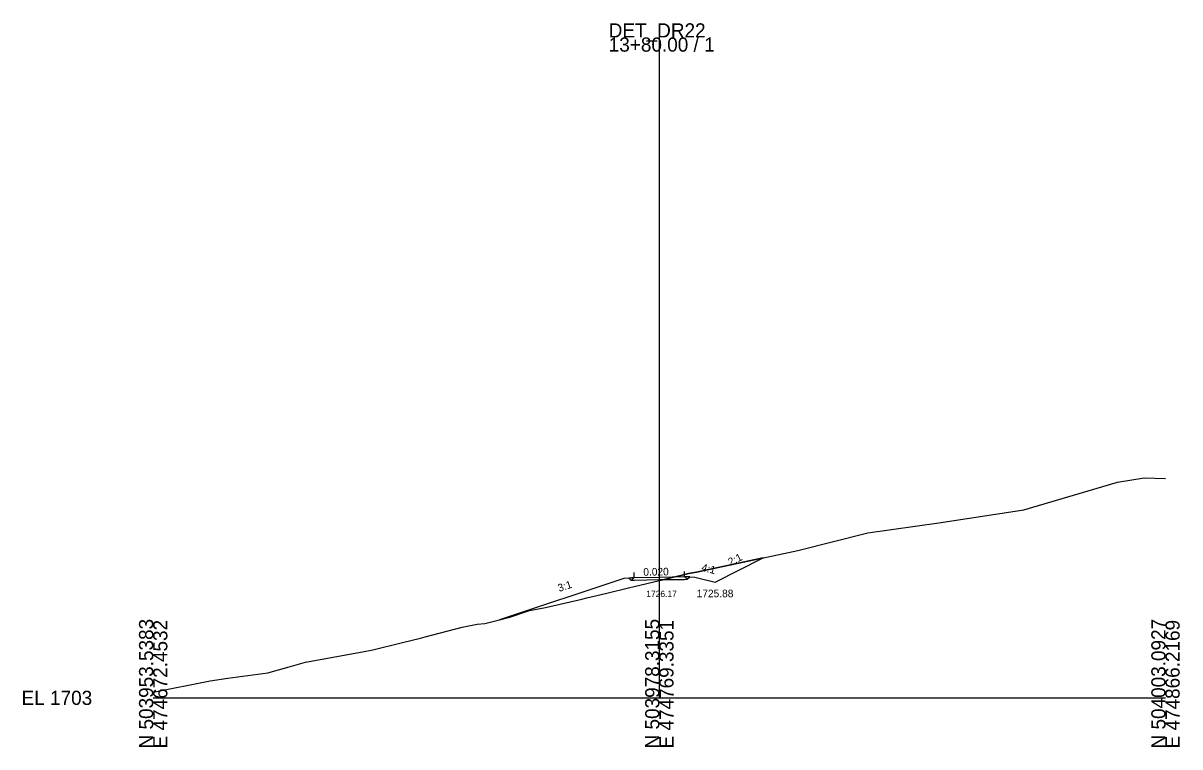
# Model space of a CAD drawing. Extents: x -26 to 1203, y -10 to 9633.
# Drawn here: x -25.7 to 202.8, y 9490.3 to 9633.4 of the extents above; entities that cross this region are included whole.
import ezdxf

# ---------------------------------------------------------------- set-up
doc = ezdxf.new("R2010")
doc.units = 0
for name, color, linetype in [('Exist Cross Section Cell', 7, 'Continuous'), ('Exist XS Center Line Elevation Label', 7, 'Continuous'), ('Exist XS Ground Line', 7, 'Continuous'), ('Prop XS Ditch Slope Text', 7, 'Continuous'), ('Prop XS Ditch Standard Text', 7, 'Continuous'), ('Prop XS Earthwork Shape', 7, 'Continuous'), ('Prop XS EOT Tick Mark', 7, 'Continuous'), ('Prop XS Finish Grade', 7, 'Continuous'), ('Prop XS Finish Grade Earthwork', 7, 'Continuous'), ('Prop XS Finish Grade Pavement', 7, 'Continuous'), ('Prop XS Pvmt Edge Slope', 7, 'Continuous'), ('Prop XS SE Text', 7, 'Continuous'), ('Prop XS Shoulder Borrow Shape', 7, 'Continuous'), ('Prop XS Side Slope Text', 7, 'Continuous'), ('Prop XS Subgrade Earthwork', 7, 'Continuous')]:
    doc.layers.add(name, color=color, linetype=linetype)

msp = doc.modelspace()

# ---------------------------------------------------------------- linework, layer by layer
at = {"layer": 'Exist Cross Section Cell'}
for p, q in [((100, 9500), (100, 9630.52)), ((0, 9500), (100, 9500)), ((100, 9500), (200, 9500))]:
    msp.add_line(p, q, dxfattribs=at)
at = {"layer": 'Exist XS Ground Line'}
msp.add_lwpolyline([(0, 9501.1), (11.27, 9503.38), (14.77, 9503.87), (22.65, 9504.95), (26.88, 9506.1), (30.1, 9507.02), (41.38, 9509.12), (43.4, 9509.52), (49.26, 9510.91), (52.81, 9511.81), (53.72, 9512.03), (61.03, 9513.96), (64.04, 9514.57), (65.53, 9514.67), (70.45, 9515.92), (74.37, 9517.25), (77.48, 9517.87), (84.69, 9519.49), (85.7, 9519.74), (89.63, 9520.66), (93.92, 9521.73), (95.02, 9522), (100, 9523.17), (105.07, 9524.35), (105.74, 9524.6), (107.31, 9524.83), (109.81, 9525.37), (127.36, 9529.1), (141.18, 9532.64), (155.23, 9534.62), (171.98, 9537.15), (190.53, 9542.61), (195.78, 9543.51), (200, 9543.35)], dxfattribs=at)
at = {"layer": 'Prop XS Earthwork Shape'}
for points in [[(107, 9523.88), (111, 9522.88), (120.53, 9527.64), (109.81, 9525.37), (107.31, 9524.83), (105.74, 9524.6), (105.07, 9524.35), (100.71, 9523.33), (105, 9523.42), (105.53, 9523.43), (106.02, 9523.92)], [(93, 9523.6), (68.39, 9515.4), (70.45, 9515.92), (74.37, 9517.25), (77.48, 9517.87), (84.69, 9519.49), (85.7, 9519.74), (89.63, 9520.66), (93.92, 9521.73), (95.02, 9522), (100, 9523.17), (100.71, 9523.33), (100, 9523.32), (95, 9523.22), (94.45, 9523.21), (93.98, 9523.68)]]:
    msp.add_lwpolyline(points, close=True, dxfattribs=at)
at = {"layer": 'Prop XS EOT Tick Mark'}
for p, q in [((95, 9523.76), (95, 9524.76)), ((105, 9523.96), (105, 9524.96))]:
    msp.add_line(p, q, dxfattribs=at)
at = {"layer": 'Prop XS Finish Grade'}
for p, q in [((95, 9523.76), (93.98, 9523.68)), ((105, 9523.96), (106.02, 9523.92))]:
    msp.add_line(p, q, dxfattribs=at)
at = {"layer": 'Prop XS Finish Grade Earthwork'}
for p, q in [((111, 9522.88), (120.53, 9527.64)), ((93, 9523.6), (68.39, 9515.4)), ((93.98, 9523.68), (93, 9523.6)), ((106.02, 9523.92), (107, 9523.88)), ((107, 9523.88), (111, 9522.88))]:
    msp.add_line(p, q, dxfattribs=at)
at = {"layer": 'Prop XS Finish Grade Pavement'}
for p, q in [((95, 9523.76), (100, 9523.86)), ((100, 9523.86), (105, 9523.96))]:
    msp.add_line(p, q, dxfattribs=at)
at = {"layer": 'Prop XS Pvmt Edge Slope'}
for p, q in [((95, 9523.76), (94.45, 9523.21)), ((105, 9523.96), (105.53, 9523.43))]:
    msp.add_line(p, q, dxfattribs=at)
at = {"layer": 'Prop XS Shoulder Borrow Shape'}
for points in [[(95, 9523.76), (94.45, 9523.21), (93.98, 9523.68)], [(105.53, 9523.43), (106.02, 9523.92), (105, 9523.96)]]:
    msp.add_lwpolyline(points, close=True, dxfattribs=at)
at = {"layer": 'Prop XS Subgrade Earthwork'}
for p, q in [((94.45, 9523.21), (93.98, 9523.68)), ((95, 9523.22), (94.45, 9523.21)), ((100, 9523.32), (95, 9523.22)), ((105, 9523.42), (100, 9523.32)), ((105, 9523.42), (105.53, 9523.43)), ((105.53, 9523.43), (106.02, 9523.92))]:
    msp.add_line(p, q, dxfattribs=at)

# ---------------------------------------------------------------- texts
at = {"layer": 'Exist Cross Section Cell'}
for s, p in [('DET_DR22', (90, 9630.52)), ('13+80.00 / 1', (90, 9627.72)), ('EL 1703', (-26, 9498.6))]:
    msp.add_text(s, height=2.8, dxfattribs=at).set_placement(p)
for s, p in [('N 503953.5383', (0, 9490)), ('E 474672.4532', (2.8, 9490)), ('N 503978.3155', (100, 9490)), ('E 474769.3351', (102.8, 9490)), ('N 504003.0927', (200, 9490)), ('E 474866.2169', (202.8, 9490))]:
    msp.add_text(s, height=2.8, rotation=90, dxfattribs=at).set_placement(p)
at = {"layer": 'Exist XS Center Line Elevation Label'}
msp.add_text('1726.17', height=1.25, dxfattribs=at).set_placement((97.41, 9519.92))
at = {"layer": 'Prop XS Ditch Slope Text'}
msp.add_text('4:1', height=1.5, rotation=345.9638, dxfattribs=at).set_placement((108.21, 9525.13))
at = {"layer": 'Prop XS Ditch Standard Text'}
msp.add_text('1725.88', height=1.5, dxfattribs=at).set_placement((107.38, 9519.88))
at = {"layer": 'Prop XS SE Text'}
msp.add_text('0.020', height=1.5, rotation=1.1458, dxfattribs=at).set_placement((96.85, 9524.12))
at = {"layer": 'Prop XS Side Slope Text'}
for s, rotation, p in [('2:1', 26.5651, (114.03, 9526.07)), ('3:1', 18.4349, (80.22, 9520.92))]:
    msp.add_text(s, height=1.5, rotation=rotation, dxfattribs=at).set_placement(p)

doc.saveas('drawing.dxf')
